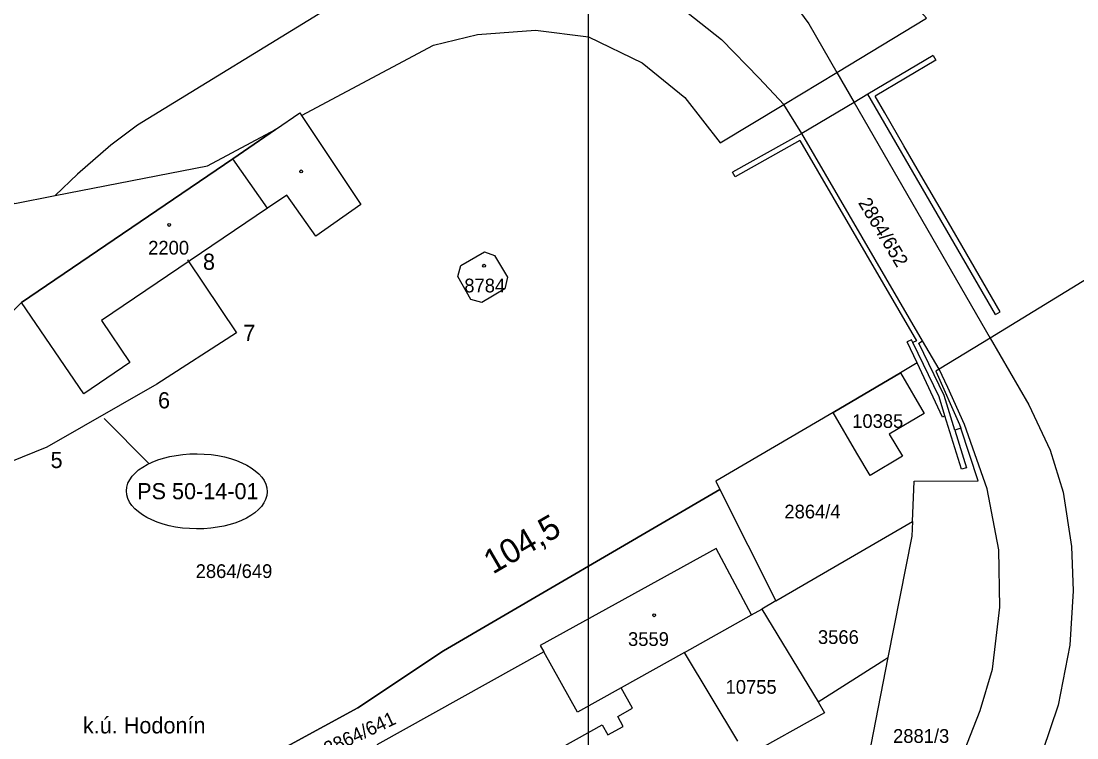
# Model space of a CAD drawing. Extents: x -564952 to -564307, y -1202373 to -1201847.
# Drawn here: x -564610.5 to -564479.9, y -1202086.9 to -1201998.2 of the extents above; entities that cross this region are included whole.
import ezdxf

# ---------------------------------------------------------------- set-up
doc = ezdxf.new("R2010")
doc.units = 0
for name, color, linetype in [('Hranice parcel', 7, 'Continuous'), ('kú', 7, 'Continuous'), ('Parcelní čísla', 7, 'Continuous'), ('PS 50-14-01 body', 7, 'Continuous'), ('PS 50-14-01 chránička', 7, 'Continuous'), ('Vnitřní kresba', 7, 'Continuous'), ('Vrstva 31', 7, 'Continuous'), ('Vrstva 63', 7, 'Continuous'), ('Vrstva 7', 7, 'Continuous'), ('Značky budov', 7, 'Continuous')]:
    doc.layers.add(name, color=color, linetype=linetype)

msp = doc.modelspace()

# ---------------------------------------------------------------- linework, layer by layer
at = {"layer": 'Hranice parcel'}
for p, q in [((-564575.81, -1202009.88), (-564559.51, -1202001.15)), ((-564516.14, -1202008.51), (-564509.57, -1202004.53)), ((-564519.2, -1202005.26), (-564516.14, -1202008.51)), ((-564524, -1202013.27), (-564516.14, -1202008.51)), ((-564513.92, -1202012.09), (-564516.14, -1202008.51)), ((-564498.96, -1202037.78), (-564513.92, -1202012.09)), ((-564603.54, -1202017.13), (-564606.29, -1202019.78)), ((-564477.18, -1202029.23), (-564490.61, -1202037.43)), ((-564610.49, -1202033.02), (-564620.58, -1202043.17)), ((-564490.61, -1202037.43), (-564496.91, -1202041.27)), ((-564496.91, -1202041.27), (-564498.96, -1202037.78)), ((-564496.91, -1202041.27), (-564497.31, -1202041.52)), ((-564497.31, -1202041.52), (-564494.4, -1202048.12)), ((-564495.85, -1202043.53), (-564496.91, -1202041.27)), ((-564510.03, -1202046.63), (-564501.71, -1202041.71)), ((-564501.71, -1202041.71), (-564498.78, -1202046.76)), ((-564510.03, -1202046.63), (-564524.57, -1202055.16)), ((-564507.09, -1202051.69), (-564510.03, -1202046.63)), ((-564494.4, -1202048.12), (-564494.25, -1202048.58)), ((-564492.09, -1202055.11), (-564494.25, -1202048.58)), ((-564524.57, -1202055.16), (-564524.06, -1202056.17)), ((-564500.23, -1202060.14), (-564500, -1202055.15)), ((-564500, -1202055.15), (-564492.09, -1202055.11)), ((-564558.26, -1202076.16), (-564524.06, -1202056.17)), ((-564524.06, -1202056.17), (-564517.11, -1202069.96)), ((-564517.11, -1202069.96), (-564500.23, -1202060.14)), ((-564524.52, -1202063.47), (-564546.29, -1202075.48)), ((-564520.12, -1202071.71), (-564524.52, -1202063.47)), ((-564517.11, -1202069.96), (-564518.86, -1202070.98)), ((-564528.43, -1202076.35), (-564520.12, -1202071.71)), ((-564520.12, -1202071.71), (-564518.86, -1202070.98)), ((-564518.86, -1202070.98), (-564511.87, -1202082.45)), ((-564546.29, -1202075.48), (-564545.83, -1202076.29)), ((-564545.83, -1202076.29), (-564566.49, -1202087.78)), ((-564528.43, -1202076.35), (-564536.27, -1202080.72)), ((-564521.82, -1202087.35), (-564528.43, -1202076.35)), ((-564534.85, -1202083.23), (-564536.27, -1202080.72))]:
    msp.add_line(p, q, dxfattribs=at)
for points in [[(-564605.69, -1201982.88), (-564598.88, -1201983.3), (-564561.75, -1201980.66), (-564553.92, -1201980.18), (-564549.62, -1201979.94), (-564544.81, -1201979.95), (-564538.75, -1201980.64), (-564532.96, -1201982.16), (-564526.67, -1201985.07), (-564523.04, -1201987.55), (-564519.22, -1201990.84), (-564516.18, -1201994.23), (-564513.04, -1201998.5), (-564509.57, -1202004.53)], [(-564572.99, -1201990.58), (-564557.98, -1201989.28), (-564550.78, -1201989.16), (-564545.37, -1201989.69), (-564539.44, -1201991.01), (-564534.17, -1201993.43), (-564528.95, -1201996.43), (-564523.84, -1202000.46), (-564519.2, -1202005.26)], [(-564509.57, -1202004.53), (-564498.5, -1201997.83), (-564505.77, -1201989.55)], [(-564571.73, -1201996.14), (-564596.1, -1202011.05), (-564599.43, -1202013.53), (-564603.54, -1202017.13)], [(-564655, -1202066.79), (-564638.03, -1202059.06), (-564637.69, -1202058.81), (-564638.33, -1202057.87), (-564636.74, -1202056.66), (-564621.41, -1202042.36), (-564620.58, -1202043.17), (-564610.49, -1202033.02), (-564584.31, -1202015.23), (-564579.06, -1202011.62), (-564576.04, -1202009.54), (-564575.81, -1202009.88), (-564559.51, -1202001.15), (-564554.04, -1201999.85), (-564546.86, -1201999.32), (-564540.29, -1202000.14), (-564533.65, -1202003.36), (-564528.41, -1202007.65), (-564524, -1202013.27)], [(-564559.51, -1202001.15), (-564554.04, -1201999.85), (-564546.86, -1201999.32), (-564540.29, -1202000.14), (-564533.65, -1202003.36), (-564528.41, -1202007.65), (-564524, -1202013.27)], [(-564509.57, -1202004.53), (-564507.43, -1202008.25), (-564490.61, -1202037.43)], [(-564575.81, -1202009.88), (-564568.47, -1202020.87), (-564574.05, -1202024.8), (-564577.64, -1202019.72), (-564580.05, -1202021.35), (-564600.56, -1202035.26), (-564597.08, -1202040.44), (-564602.78, -1202044.32), (-564610.49, -1202033.02)], [(-564579.06, -1202011.62), (-564576.04, -1202009.54), (-564575.81, -1202009.88)], [(-564579.06, -1202011.62), (-564584.31, -1202015.23), (-564610.49, -1202033.02)], [(-564606.29, -1202019.78), (-564587.44, -1202016.1), (-564579.06, -1202011.62)], [(-564632.9, -1202012.18), (-564611.28, -1202020.76), (-564606.29, -1202019.78)], [(-564551.94, -1202027.21), (-564550.33, -1202029.89), (-564550.68, -1202031.34), (-564553.53, -1202033.02), (-564554.87, -1202032.65), (-564556.49, -1202029.8), (-564556.11, -1202028.46), (-564553.19, -1202026.76), (-564551.94, -1202027.21)], [(-564490.61, -1202037.43), (-564485.84, -1202045.71), (-564483.2, -1202051.32), (-564481.59, -1202056.49), (-564480.56, -1202063.21), (-564480.33, -1202068.72), (-564480.73, -1202075.46), (-564482.21, -1202082.88), (-564484.11, -1202088.61), (-564486.01, -1202092.94), (-564492.26, -1202106.34), (-564537.63, -1202203.39), (-564539.05, -1202206.7), (-564540.49, -1202210.49), (-564542.11, -1202215.98)], [(-564494.25, -1202048.58), (-564494.99, -1202048.81), (-564493.55, -1202053.47), (-564494.17, -1202053.66), (-564496.2, -1202047.07), (-564496.51, -1202047.21), (-564499.65, -1202040.49), (-564501.71, -1202041.71)], [(-564501.71, -1202041.71), (-564510.03, -1202046.63), (-564524.57, -1202055.16), (-564524.06, -1202056.17), (-564524.06, -1202056.17), (-564558.26, -1202076.16), (-564568.86, -1202083.22), (-564594.31, -1202097.06), (-564593.15, -1202099.21), (-564599.65, -1202102.83), (-564621.36, -1202114.89), (-564629.71, -1202119.53), (-564639.63, -1202125.04), (-564642, -1202126.36)], [(-564513.56, -1202130.84), (-564493.88, -1202088.69), (-564491.84, -1202083.54), (-564490.32, -1202078.4), (-564489.39, -1202070.74), (-564489.54, -1202063.63), (-564490.98, -1202056.1), (-564493.78, -1202048.14), (-564495.85, -1202043.53)], [(-564498.78, -1202046.76), (-564503.09, -1202049.32), (-564501.46, -1202052.06), (-564505.46, -1202054.43), (-564507.09, -1202051.69)], [(-564500.23, -1202060.14), (-564500.31, -1202061.96), (-564503.26, -1202076.98)], [(-564593.15, -1202099.21), (-564594.31, -1202097.06), (-564568.86, -1202083.22), (-564558.26, -1202076.16)], [(-564536.27, -1202080.72), (-564541.66, -1202083.73), (-564545.83, -1202076.29)], [(-564511.87, -1202082.45), (-564503.65, -1202077.23), (-564503.26, -1202076.98)], [(-564503.26, -1202076.98), (-564506.29, -1202092.45), (-564506.54, -1202093.7)], [(-564579.72, -1202106.62), (-564579.07, -1202107.87), (-564563.9, -1202099.44), (-564564.37, -1202098.6), (-564561.39, -1202096.95), (-564560.92, -1202097.79), (-564538.6, -1202085.32), (-564537.9, -1202086.54), (-564536.02, -1202085.5), (-564536.68, -1202084.26), (-564534.85, -1202083.23)], [(-564511.87, -1202082.45), (-564511.1, -1202083.83), (-564520.73, -1202089.2)]]:
    msp.add_lwpolyline(points, dxfattribs=at)
at = {"layer": 'PS 50-14-01 chránička'}
for p, q in [((-564589.92, -1202027.74), (-564583.88, -1202036.76)), ((-564583.88, -1202036.76), (-564593.71, -1202043.12)), ((-564593.71, -1202043.12), (-564607.33, -1202050.94)), ((-564600.26, -1202047.39), (-564594.71, -1202052.94)), ((-564607.33, -1202050.94), (-564614.64, -1202053.89))]:
    msp.add_line(p, q, dxfattribs=at)
msp.add_ellipse((-564588.78, -1202056.4), major_axis=(8.7, -0.06), ratio=0.534132, dxfattribs=at)
at = {"layer": 'Vnitřní kresba'}
for p, q in [((-564497.66, -1202002.46), (-564505.73, -1202007.24)), ((-564497.66, -1202002.46), (-564497.33, -1202003.02)), ((-564497.33, -1202003.02), (-564504.84, -1202007.47)), ((-564505.73, -1202007.24), (-564507.43, -1202008.25)), ((-564489.93, -1202034.49), (-564505.73, -1202007.24)), ((-564503.64, -1202009.55), (-564504.84, -1202007.47)), ((-564507.43, -1202008.25), (-564513.92, -1202012.09)), ((-564501.27, -1202013.63), (-564503.64, -1202009.55)), ((-564513.92, -1202012.09), (-564522.5, -1202016.9)), ((-564514.16, -1202012.97), (-564522.18, -1202017.47)), ((-564514.16, -1202012.97), (-564499.73, -1202037.75)), ((-564498.89, -1202017.74), (-564501.27, -1202013.63)), ((-564580.05, -1202021.35), (-564584.31, -1202015.23)), ((-564522.18, -1202017.47), (-564522.5, -1202016.9)), ((-564496.51, -1202021.84), (-564498.89, -1202017.74)), ((-564494.11, -1202025.98), (-564496.51, -1202021.84)), ((-564489.37, -1202034.16), (-564494.11, -1202025.98)), ((-564489.93, -1202034.49), (-564489.37, -1202034.16)), ((-564500.35, -1202037.63), (-564500.87, -1202037.87)), ((-564500.19, -1202037.97), (-564500.35, -1202037.63)), ((-564499.73, -1202037.75), (-564500.19, -1202037.97)), ((-564499.65, -1202040.49), (-564500.87, -1202037.87)), ((-564496.93, -1202044.71), (-564500.19, -1202037.97)), ((-564499.44, -1202038.06), (-564498.96, -1202037.78)), ((-564496.31, -1202044.52), (-564499.44, -1202038.06)), ((-564496.2, -1202047.07), (-564496.93, -1202044.71)), ((-564494.99, -1202048.81), (-564496.31, -1202044.52))]:
    msp.add_line(p, q, dxfattribs=at)
at = {"layer": 'Vrstva 31'}
for p, q in [((-564589.92, -1202027.74), (-564589.92, -1202027.74)), ((-564583.88, -1202036.76), (-564583.88, -1202036.76)), ((-564593.71, -1202043.12), (-564593.71, -1202043.12)), ((-564607.33, -1202050.94), (-564607.33, -1202050.94))]:
    msp.add_line(p, q, dxfattribs=at)
at = {"layer": 'Vrstva 63'}
msp.add_lwpolyline([(-564540.34, -1202137.49), (-564645.34, -1202137.49), (-564645.34, -1201988.99), (-564540.34, -1201988.99)], close=True, dxfattribs=at)
at = {"layer": 'Značky budov'}
for centre in [(-564575.86, -1202016.79), (-564592.21, -1202023.42), (-564553.24, -1202028.47), (-564532.19, -1202071.75)]:
    msp.add_circle(centre, 0.175, dxfattribs=at)

# ---------------------------------------------------------------- texts
at = {"layer": 'kú'}
msp.add_text('k.ú. Hodonín', height=2, dxfattribs=at).set_placement((-564602.87, -1202086.37))
at = {"layer": 'Parcelní čísla'}
for s, rotation, p in [('2864/652', 301, (-564506.99, -1202020.67)), ('2864/641', 25, (-564572.58, -1202089.14))]:
    msp.add_text(s, height=1.7, rotation=rotation, dxfattribs=at).set_placement(p)
for s, p in [('2200', (-564594.8, -1202027.09)), ('8784', (-564555.68, -1202031.77)), ('10385', (-564507.68, -1202048.55)), ('2864/4', (-564516.07, -1202059.75)), ('2864/649', (-564588.92, -1202067.13)), ('3559', (-564535.42, -1202075.54)), ('3566', (-564511.92, -1202075.29)), ('10755', (-564523.35, -1202081.46)), ('2881/3', (-564502.62, -1202087.54))]:
    msp.add_text(s, height=1.7, dxfattribs=at).set_placement(p)
at = {"layer": 'PS 50-14-01 body'}
for s, p in [('8', (-564588.02, -1202028.97)), ('7', (-564583.03, -1202037.78)), ('6', (-564593.58, -1202046.13)), ('5', (-564606.88, -1202053.52))]:
    msp.add_text(s, height=2, dxfattribs=at).set_placement(p)
at = {"layer": 'PS 50-14-01 chránička'}
msp.add_text('PS 50-14-01', height=2, dxfattribs=at).set_placement((-564596.16, -1202057.38))
at = {"layer": 'Vrstva 7'}
msp.add_text('104,5', height=3, rotation=30.1544, dxfattribs=at).set_placement((-564552.15, -1202066.72))

doc.saveas('drawing.dxf')
